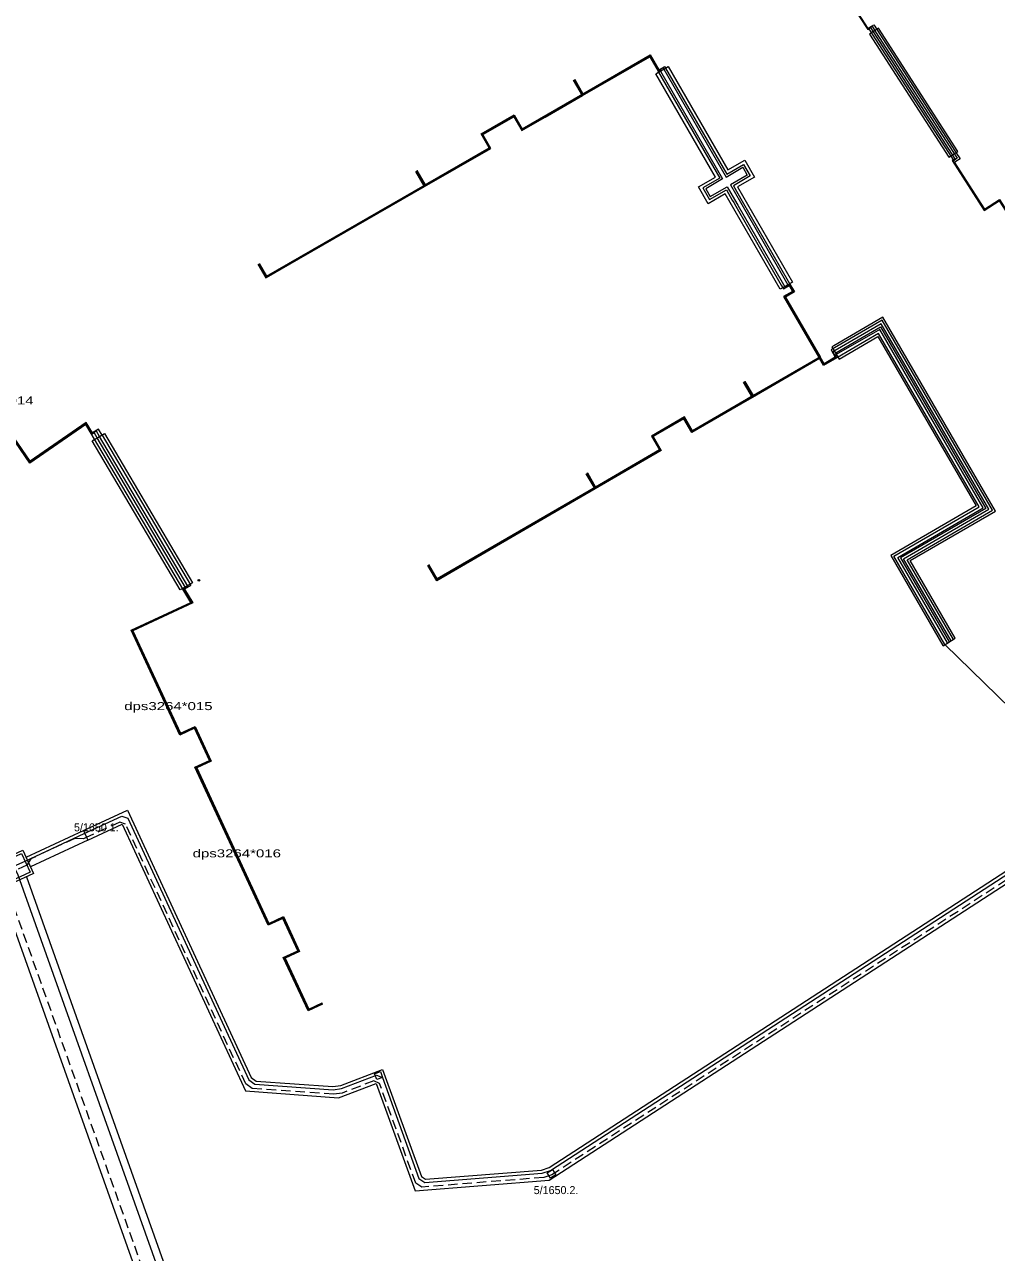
# Model space of a CAD drawing. Extents: x -473467 to -473049, y -1106745 to -1106181.
# Drawn here: x -473244.9 to -473135.6, y -1106543.7 to -1106405.6 of the extents above; entities that cross this region are included whole.
import ezdxf
from ezdxf.enums import TextEntityAlignment as Align

# ---------------------------------------------------------------- set-up
doc = ezdxf.new("R2010")
doc.units = 0
doc.header["$LTSCALE"] = 0.36
doc.header["$PDMODE"] = 32
doc.header["$PDSIZE"] = 0.18
doc.linetypes.add('MEDIUM_DASHED', pattern=[4.5, 3, -1.5])
for name, color, linetype, lineweight in [('1', 7, 'MEDIUM_DASHED', 13), ('11', 7, 'Continuous', 13), ('17', 7, 'Continuous', 13), ('4', 7, 'Continuous', 13), ('7', 7, 'Continuous', 13)]:
    doc.layers.add(name, color=color, linetype=linetype, lineweight=lineweight)
doc.layers.add('19', color=7, linetype='Continuous')
doc.layers.add('6', color=7, linetype='Continuous')

msp = doc.modelspace()

# ---------------------------------------------------------------- linework, layer by layer
at = {"layer": '1', "linetype": 'Continuous'}
for points in [[(-473238.151, -1106496.572), (-473233.916, -1106494.611), (-473233.253, -1106494.854), (-473219.66, -1106524.241), (-473218.952, -1106524.731), (-473210.178, -1106525.371), (-473209.213, -1106525.228), (-473205.294, -1106523.722), (-473204.636, -1106524.005), (-473200.526, -1106535.348), (-473199.857, -1106535.779), (-473186.652, -1106534.741), (-473185.734, -1106534.43), (-473129.308, -1106497.84), (-473126.788, -1106496.206)], [(-473246.061, -1106500.236), (-473244.807, -1106499.655), (-473238.151, -1106496.572)], [(-473246.013, -1106500.34), (-473245.619, -1106501.193), (-473182.812, -1106677.763), (-473178.72, -1106679.719), (-473101.034, -1106652.497), (-473096.956, -1106654.459), (-473096.08, -1106656.96), (-473095.369, -1106658.988)]]:
    msp.add_lwpolyline(points, dxfattribs=at)
at = {"layer": '1'}
for points in [[(-473126.788, -1106496.206), (-473126.498, -1106496.613), (-473129.036, -1106498.26), (-473185.568, -1106534.919), (-473186.486, -1106535.23), (-473200.197, -1106536.307), (-473200.867, -1106535.877), (-473204.951, -1106524.662), (-473205.589, -1106524.371), (-473209.138, -1106525.735), (-473210.103, -1106525.878), (-473219.282, -1106525.209), (-473219.991, -1106524.719), (-473233.497, -1106495.518), (-473234.16, -1106495.275), (-473237.921, -1106497.017)], [(-473237.921, -1106497.017), (-473238.243, -1106497.166), (-473239.22, -1106497.122), (-473244.159, -1106499.41), (-473244.597, -1106500.109), (-473247.32, -1106501.37)], [(-473097.014, -1106659.141), (-473097.592, -1106657.49), (-473097.935, -1106656.511), (-473102.013, -1106654.549), (-473179.701, -1106681.772), (-473183.794, -1106679.815), (-473247.114, -1106501.803), (-473247.258, -1106501.495)]]:
    msp.add_lwpolyline(points, dxfattribs=at)
at = {"layer": '11'}
msp.add_line((-473141.383, -1106475.297), (-473123.66, -1106492.696), dxfattribs=at)
for points in [[(-473175.225, -1106366.998), (-473168.735, -1106377.061), (-473167.054, -1106375.977), (-473164.518, -1106379.91), (-473166.199, -1106380.994), (-473155.189, -1106398.073), (-473153.508, -1106396.989), (-473150.973, -1106400.923), (-473152.654, -1106402.006), (-473150.042, -1106406.057), (-473149.622, -1106405.786), (-473149.395, -1106405.64)], [(-473175.141, -1106367.183), (-473168.744, -1106377.102), (-473167.063, -1106376.018), (-473164.56, -1106379.901), (-473166.241, -1106380.985), (-473155.198, -1106398.114), (-473153.517, -1106397.031), (-473151.014, -1106400.914), (-473152.695, -1106401.997), (-473150.051, -1106406.099), (-473149.631, -1106405.828), (-473149.58, -1106405.795)], [(-473175.045, -1106367.388), (-473168.753, -1106377.144), (-473167.072, -1106376.06), (-473164.601, -1106379.892), (-473166.282, -1106380.976), (-473155.207, -1106398.156), (-473153.526, -1106397.072), (-473151.055, -1106400.905), (-473152.736, -1106401.988), (-473150.06, -1106406.14), (-473149.766, -1106405.951)], [(-473174.972, -1106367.556), (-473168.762, -1106377.185), (-473167.081, -1106376.101), (-473164.643, -1106379.884), (-473166.324, -1106380.967), (-473155.216, -1106398.197), (-473153.535, -1106397.114), (-473151.097, -1106400.896), (-473152.778, -1106401.979), (-473150.069, -1106406.182), (-473149.953, -1106406.107)], [(-473236.982, -1106452.242), (-473237.966, -1106450.574), (-473244.267, -1106454.92), (-473250.764, -1106445.499), (-473249.283, -1106444.477), (-473251.554, -1106441.184), (-473253.035, -1106442.206), (-473266.092, -1106423.275), (-473264.61, -1106422.253), (-473266.881, -1106418.96), (-473268.363, -1106419.982), (-473275.136, -1106410.16), (-473268.535, -1106405.608), (-473268.712, -1106405.347)], [(-473236.707, -1106452.078), (-473237.013, -1106451.559), (-473237.033, -1106451.527), (-473237.266, -1106451.663), (-473237.95, -1106450.503), (-473244.255, -1106454.85), (-473250.695, -1106445.512), (-473249.213, -1106444.49), (-473251.541, -1106441.115), (-473253.023, -1106442.137), (-473266.022, -1106423.287), (-473264.54, -1106422.265), (-473266.868, -1106418.89), (-473268.35, -1106419.912), (-473275.066, -1106410.173), (-473268.466, -1106405.621), (-473268.737, -1106405.222)], [(-473236.432, -1106451.914), (-473236.782, -1106451.321), (-473237.247, -1106451.596), (-473237.935, -1106450.431), (-473244.242, -1106454.781), (-473250.625, -1106445.525), (-473249.144, -1106444.503), (-473251.528, -1106441.045), (-473253.01, -1106442.067), (-473265.953, -1106423.3), (-473264.471, -1106422.278), (-473266.855, -1106418.821), (-473268.337, -1106419.843), (-473274.997, -1106410.186), (-473268.396, -1106405.634), (-473268.667, -1106405.235)], [(-473236.146, -1106451.771), (-473236.532, -1106451.116), (-473237.23, -1106451.527), (-473237.919, -1106450.359), (-473244.229, -1106454.711), (-473250.556, -1106445.537), (-473249.074, -1106444.515), (-473251.515, -1106440.976), (-473252.997, -1106441.998), (-473265.883, -1106423.313), (-473264.401, -1106422.291), (-473266.842, -1106418.751), (-473268.324, -1106419.773), (-473274.927, -1106410.199), (-473268.327, -1106405.647), (-473268.598, -1106405.248)], [(-473149.58, -1106405.795), (-473149.172, -1106406.428), (-473140.087, -1106420.522), (-473140.001, -1106420.655)], [(-473149.395, -1106405.64), (-473149.281, -1106405.817), (-473148.971, -1106406.298), (-473139.929, -1106420.323), (-473139.885, -1106420.392), (-473139.669, -1106420.727)], [(-473149.953, -1106406.107), (-473149.756, -1106406.409), (-473149.576, -1106406.688), (-473140.664, -1106420.512), (-473140.469, -1106420.814)], [(-473149.766, -1106405.951), (-473149.684, -1106406.077), (-473149.374, -1106406.558), (-473140.332, -1106420.584), (-473140.251, -1106420.71)], [(-473199.534, -1106423.454), (-473192.64, -1106419.481), (-473193.538, -1106417.921), (-473189.813, -1106415.775), (-473188.914, -1106417.334), (-473182.084, -1106413.399), (-473182.978, -1106411.8), (-473182.084, -1106413.399), (-473174.513, -1106409.036), (-473173.547, -1106410.713), (-473173.054, -1106410.429), (-473172.897, -1106410.338)], [(-473199.512, -1106423.499), (-473192.571, -1106419.499), (-473193.47, -1106417.94), (-473189.831, -1106415.843), (-473188.932, -1106417.403), (-473182.103, -1106413.467), (-473183.038, -1106411.83), (-473182.103, -1106413.467), (-473174.532, -1106409.105), (-473173.566, -1106410.781), (-473173.392, -1106410.681), (-473173.075, -1106410.498)], [(-473186.359, -1106415.977), (-473182.121, -1106413.535), (-473183.093, -1106411.849), (-473182.121, -1106413.535), (-473174.55, -1106409.173), (-473173.584, -1106410.849), (-473173.418, -1106410.753)], [(-473186.332, -1106416.02), (-473182.139, -1106413.604), (-473183.138, -1106411.871), (-473182.139, -1106413.604), (-473174.569, -1106409.241), (-473173.628, -1106410.873)], [(-473173.628, -1106410.873), (-473173.57, -1106410.974), (-473166.705, -1106422.887), (-473168.612, -1106423.986), (-473167.863, -1106425.287), (-473165.957, -1106424.188), (-473165.287, -1106425.351), (-473165.132, -1106425.619), (-473164.895, -1106426.031)], [(-473173.418, -1106410.753), (-473173.36, -1106410.853), (-473166.375, -1106422.976), (-473168.282, -1106424.075), (-473167.774, -1106424.956), (-473165.868, -1106423.858), (-473164.778, -1106425.749), (-473164.671, -1106425.935)], [(-473173.075, -1106410.498), (-473172.993, -1106410.641), (-473165.994, -1106422.757), (-473164.108, -1106421.67), (-473163.6, -1106422.551), (-473165.499, -1106423.645), (-473164.374, -1106425.602)], [(-473172.897, -1106410.338), (-473172.789, -1106410.524), (-473172.789, -1106410.525), (-473165.905, -1106422.426), (-473164.019, -1106421.34), (-473163.27, -1106422.64), (-473165.169, -1106423.734), (-473164.165, -1106425.478)], [(-473218.619, -1106432.547), (-473217.72, -1106434.106), (-473199.886, -1106423.83), (-473200.86, -1106422.138), (-473199.886, -1106423.83), (-473192.435, -1106419.536), (-473193.333, -1106417.977), (-473189.868, -1106415.979), (-473188.969, -1106417.539), (-473186.332, -1106416.02)], [(-473218.575, -1106432.522), (-473217.702, -1106434.038), (-473199.868, -1106423.762), (-473200.818, -1106422.117), (-473199.868, -1106423.762), (-473192.503, -1106419.518), (-473193.402, -1106417.958), (-473189.849, -1106415.911), (-473188.951, -1106417.471), (-473186.359, -1106415.977)], [(-473140.469, -1106420.814), (-473140.587, -1106420.89), (-473136.964, -1106426.509), (-473135.283, -1106425.426), (-473132.845, -1106429.208), (-473134.526, -1106430.291), (-473122.335, -1106449.202), (-473120.654, -1106448.119), (-473118.216, -1106451.901), (-473119.897, -1106452.985), (-473114.632, -1106461.152), (-473114.211, -1106460.881), (-473114.034, -1106461.157)], [(-473140.251, -1106420.71), (-473140.545, -1106420.899), (-473136.955, -1106426.468), (-473135.274, -1106425.384), (-473132.804, -1106429.217), (-473134.485, -1106430.3), (-473122.326, -1106449.161), (-473120.645, -1106448.077), (-473118.174, -1106451.91), (-473119.855, -1106452.994), (-473114.623, -1106461.11), (-473114.202, -1106460.839), (-473114.033, -1106461.102), (-473113.989, -1106461.171)], [(-473140.001, -1106420.655), (-473140.471, -1106420.959), (-473140.413, -1106421.049), (-473136.947, -1106426.426), (-473135.266, -1106425.343), (-473132.762, -1106429.226), (-473134.443, -1106430.309), (-473122.317, -1106449.119), (-473120.636, -1106448.036), (-473118.133, -1106451.919), (-473119.814, -1106453.003), (-473114.614, -1106461.069), (-473114.193, -1106460.798), (-473114.008, -1106461.086), (-473113.963, -1106461.155)], [(-473139.669, -1106420.727), (-473140.14, -1106421.03), (-473140.316, -1106421.144), (-473136.938, -1106426.385), (-473135.257, -1106425.301), (-473132.721, -1106429.235), (-473134.402, -1106430.318), (-473122.308, -1106449.078), (-473120.627, -1106447.994), (-473118.091, -1106451.928), (-473119.772, -1106453.011), (-473114.605, -1106461.027), (-473114.185, -1106460.756), (-473113.957, -1106461.109)], [(-473218.532, -1106432.497), (-473217.683, -1106433.97), (-473204.656, -1106426.463), (-473200.801, -1106424.242), (-473199.849, -1106423.693), (-473200.775, -1106422.066), (-473199.849, -1106423.693), (-473199.512, -1106423.499)], [(-473218.489, -1106432.472), (-473217.665, -1106433.902), (-473199.831, -1106423.625), (-473200.75, -1106422.028), (-473199.831, -1106423.625), (-473199.534, -1106423.454)], [(-473164.895, -1106426.031), (-473159.782, -1106434.907), (-473159.604, -1106435.214), (-473159.533, -1106435.339)], [(-473164.671, -1106425.935), (-473159.693, -1106434.576), (-473159.397, -1106435.089), (-473159.348, -1106435.175)], [(-473164.374, -1106425.602), (-473159.331, -1106434.368), (-473159.036, -1106434.881), (-473159.011, -1106434.924)], [(-473164.165, -1106425.478), (-473159.001, -1106434.457), (-473158.804, -1106434.798)], [(-473159.348, -1106435.175), (-473158.863, -1106434.896), (-473158.44, -1106435.631), (-473159.456, -1106436.221), (-473155.463, -1106443.104)], [(-473159.011, -1106434.924), (-473158.845, -1106434.828), (-473158.372, -1106435.65), (-473159.388, -1106436.239), (-473155.445, -1106443.036)], [(-473158.804, -1106434.798), (-473158.304, -1106435.668), (-473159.32, -1106436.257), (-473155.426, -1106442.968)], [(-473159.533, -1106435.339), (-473158.882, -1106434.965), (-473158.509, -1106435.613), (-473159.525, -1106436.203), (-473155.481, -1106443.173)], [(-473140.424, -1106474.741), (-473145.616, -1106465.792), (-473136.025, -1106460.228), (-473148.433, -1106438.841), (-473153.806, -1106441.958), (-473153.81, -1106441.958), (-473153.965, -1106442.051), (-473154.191, -1106442.187)], [(-473140.69, -1106474.895), (-473146.036, -1106465.68), (-473136.446, -1106460.116), (-473148.545, -1106439.262), (-473153.723, -1106442.266), (-473153.725, -1106442.266), (-473153.806, -1106442.315), (-473153.994, -1106442.427)], [(-473141.086, -1106475.125), (-473146.662, -1106465.514), (-473137.071, -1106459.95), (-473148.711, -1106439.887), (-473153.6, -1106442.723), (-473153.598, -1106442.723), (-473153.679, -1106442.77), (-473153.722, -1106442.796)], [(-473141.383, -1106475.297), (-473147.13, -1106465.39), (-473137.54, -1106459.826), (-473148.835, -1106440.356), (-473153.464, -1106443.041), (-473153.551, -1106443.091)], [(-473153.551, -1106443.091), (-473155.03, -1106443.95), (-473155.481, -1106443.173), (-473163.006, -1106447.539), (-473164.012, -1106445.81), (-473163.006, -1106447.539), (-473163.619, -1106447.894)], [(-473153.722, -1106442.796), (-473153.576, -1106443.048), (-473155.012, -1106443.881), (-473155.463, -1106443.104), (-473162.989, -1106447.471), (-473163.961, -1106445.794), (-473162.989, -1106447.471), (-473163.646, -1106447.852)], [(-473153.994, -1106442.427), (-473153.644, -1106443.03), (-473154.994, -1106443.813), (-473155.445, -1106443.036), (-473162.97, -1106447.402), (-473163.92, -1106445.764), (-473162.97, -1106447.402), (-473163.678, -1106447.813)], [(-473154.191, -1106442.187), (-473153.712, -1106443.012), (-473154.976, -1106443.745), (-473155.426, -1106442.968), (-473162.952, -1106447.334), (-473163.875, -1106445.742), (-473162.952, -1106447.334), (-473163.708, -1106447.772)], [(-473163.619, -1106447.894), (-473169.822, -1106451.493), (-473170.725, -1106449.936), (-473174.185, -1106451.943), (-473173.282, -1106453.5), (-473180.721, -1106457.816), (-473181.705, -1106456.109), (-473180.721, -1106457.816), (-473198.522, -1106468.143), (-473199.526, -1106466.413)], [(-473163.646, -1106447.852), (-473169.804, -1106451.425), (-473170.707, -1106449.868), (-473174.254, -1106451.925), (-473173.35, -1106453.482), (-473180.703, -1106457.747), (-473181.667, -1106456.087), (-473180.703, -1106457.747), (-473198.504, -1106468.075), (-473199.482, -1106466.388)], [(-473163.678, -1106447.813), (-473169.786, -1106451.356), (-473170.689, -1106449.799), (-473174.322, -1106451.907), (-473173.419, -1106453.464), (-473180.685, -1106457.679), (-473181.624, -1106456.063), (-473180.685, -1106457.679), (-473198.486, -1106468.006), (-473199.439, -1106466.363)], [(-473163.708, -1106447.772), (-473169.768, -1106451.288), (-473170.671, -1106449.731), (-473174.39, -1106451.889), (-473173.487, -1106453.446), (-473180.666, -1106457.611), (-473181.586, -1106456.025), (-473180.666, -1106457.611), (-473198.468, -1106467.938), (-473199.396, -1106466.338)], [(-473227.048, -1106469.081), (-473227.066, -1106469.051), (-473236.982, -1106452.242)], [(-473227.005, -1106469.055), (-473226.773, -1106468.918), (-473236.707, -1106452.078)], [(-473226.936, -1106469.074), (-473226.472, -1106468.799), (-473226.497, -1106468.756), (-473236.432, -1106451.914)], [(-473236.146, -1106451.771), (-473226.222, -1106468.593), (-473226.196, -1106468.636), (-473226.171, -1106468.679)], [(-473211.348, -1106515.742), (-473212.98, -1106516.501), (-473215.772, -1106510.494), (-473214.139, -1106509.735), (-473215.825, -1106506.108), (-473217.457, -1106506.866), (-473225.705, -1106489.116), (-473224.072, -1106488.358), (-473225.758, -1106484.73), (-473227.39, -1106485.488), (-473232.87, -1106473.694), (-473226.165, -1106470.579), (-473227.048, -1106469.081)], [(-473211.369, -1106515.697), (-473212.956, -1106516.434), (-473215.705, -1106510.518), (-473214.073, -1106509.759), (-473215.8, -1106506.041), (-473217.433, -1106506.8), (-473225.638, -1106489.14), (-473224.006, -1106488.382), (-473225.734, -1106484.664), (-473227.366, -1106485.422), (-473232.804, -1106473.719), (-473226.094, -1106470.601), (-473227.005, -1106469.055)], [(-473211.39, -1106515.652), (-473212.932, -1106516.368), (-473215.639, -1106510.542), (-473214.006, -1106509.784), (-473215.776, -1106505.975), (-473217.409, -1106506.733), (-473225.572, -1106489.165), (-473223.939, -1106488.406), (-473225.709, -1106484.597), (-473227.342, -1106485.356), (-473232.737, -1106473.743), (-473226.023, -1106470.623), (-473226.936, -1106469.074)], [(-473226.171, -1106468.679), (-473226.868, -1106469.091), (-473225.951, -1106470.645), (-473232.671, -1106473.767), (-473227.317, -1106485.289), (-473225.685, -1106484.531), (-473223.873, -1106488.43), (-473225.505, -1106489.189), (-473217.384, -1106506.667), (-473215.752, -1106505.908), (-473213.94, -1106509.808), (-473215.572, -1106510.567), (-473212.908, -1106516.301), (-473211.411, -1106515.606)]]:
    msp.add_lwpolyline(points, dxfattribs=at)
at = {"layer": '17'}
msp.add_line((-473173.873, -1106411.149), (-473173.591, -1106410.986), dxfattribs=at)
for points in [[(-473140.942, -1106420.524), (-473139.933, -1106419.874), (-473148.857, -1106406.031), (-473149.866, -1106406.681)], [(-473140.237, -1106474.591), (-473145.292, -1106465.878), (-473135.702, -1106460.314), (-473148.347, -1106438.518), (-473153.869, -1106441.721), (-473154.087, -1106441.848), (-473153.263, -1106443.219), (-473148.928, -1106440.704), (-473137.888, -1106459.733), (-473147.478, -1106465.297), (-473141.603, -1106475.424), (-473141.584, -1106475.458)]]:
    msp.add_lwpolyline(points, close=True, dxfattribs=at)
for points in [[(-473173.591, -1106410.986), (-473172.486, -1106410.35), (-473165.778, -1106421.949), (-473163.891, -1106420.862), (-473162.793, -1106422.769), (-473164.691, -1106423.863), (-473158.524, -1106434.585), (-473159.91, -1106435.384), (-473166.085, -1106424.666), (-473167.991, -1106425.764), (-473169.09, -1106423.858), (-473167.183, -1106422.759), (-473173.873, -1106411.149)], [(-473153.675, -1106442.533), (-473153.654, -1106442.521), (-473153.654, -1106442.521), (-473148.637, -1106439.61), (-473136.794, -1106460.024), (-473146.385, -1106465.588), (-473140.911, -1106475.023)], [(-473227.363, -1106469.177), (-473237.248, -1106452.421), (-473237.248, -1106452.421), (-473236.42, -1106451.933)], [(-473236.42, -1106451.933), (-473235.87, -1106451.608), (-473225.985, -1106468.364), (-473227.363, -1106469.177)]]:
    msp.add_lwpolyline(points, dxfattribs=at)
msp.add_point((-473225.263, -1106468.099), dxfattribs=at)
at = {"layer": '4'}
for points in [[(-473244.695, -1106499.217), (-473238.239, -1106496.227), (-473237.735, -1106497.316), (-473244.191, -1106500.306)], [(-473249.565, -1106500.835), (-473245.21, -1106498.818), (-473244.244, -1106500.905), (-473248.599, -1106502.923)], [(-473205.508, -1106523.572), (-473204.85, -1106523.332), (-473204.611, -1106523.99), (-473205.269, -1106524.229)], [(-473186.097, -1106534.726), (-473185.51, -1106534.345), (-473185.129, -1106534.932), (-473185.716, -1106535.313)]]:
    msp.add_lwpolyline(points, close=True, dxfattribs=at)
at = {"layer": '7'}
for points in [[(-473238.239, -1106496.227), (-473233.292, -1106493.936), (-473219.383, -1106524.008), (-473218.831, -1106524.389), (-473210.191, -1106525.019), (-473209.302, -1106524.888), (-473204.62, -1106523.088), (-473200.237, -1106535.118), (-473199.767, -1106535.421), (-473186.723, -1106534.396), (-473185.887, -1106534.113), (-473129.499, -1106497.546)], [(-473237.735, -1106497.316), (-473233.877, -1106495.529), (-473220.012, -1106525.506), (-473209.552, -1106526.269), (-473205.329, -1106524.647), (-473200.933, -1106536.716), (-473185.872, -1106535.533), (-473128.846, -1106498.553)], [(-473244.695, -1106499.217), (-473238.239, -1106496.227), (-473237.735, -1106497.316), (-473244.191, -1106500.306)], [(-473249.964, -1106500.689), (-473249.691, -1106500.563), (-473249.692, -1106500.563), (-473245.064, -1106498.42), (-473243.846, -1106501.052), (-473248.746, -1106503.322), (-473249.965, -1106500.69)], [(-473244.636, -1106501.418), (-473182.228, -1106676.869), (-473178.391, -1106678.703), (-473099.852, -1106651.182), (-473096.666, -1106652.715), (-473095.277, -1106656.679)], [(-473247.638, -1106502.809), (-473184.069, -1106681.541), (-473180.872, -1106683.069), (-473102.347, -1106655.553), (-473098.524, -1106657.393), (-473098.392, -1106657.77)]]:
    msp.add_lwpolyline(points, dxfattribs=at)

# ---------------------------------------------------------------- texts
at = {"layer": '19', "width": 1.4}
for s, p in [('dps3264*014', (-473248.812, -1106448.331)), ('dps3264*015', (-473228.691, -1106482.688)), ('dps3264*016', (-473220.999, -1106499.242))]:
    msp.add_text(s, height=0.9, dxfattribs=at).set_placement(p, align=Align.CENTER)
at = {"layer": '6'}
for s, p in [('5/1650.1.', (-473239.301, -1106496.316)), ('5/1650.2.', (-473187.616, -1106537.098))]:
    msp.add_text(s, height=0.9, dxfattribs=at).set_placement(p)

doc.saveas('drawing.dxf')
